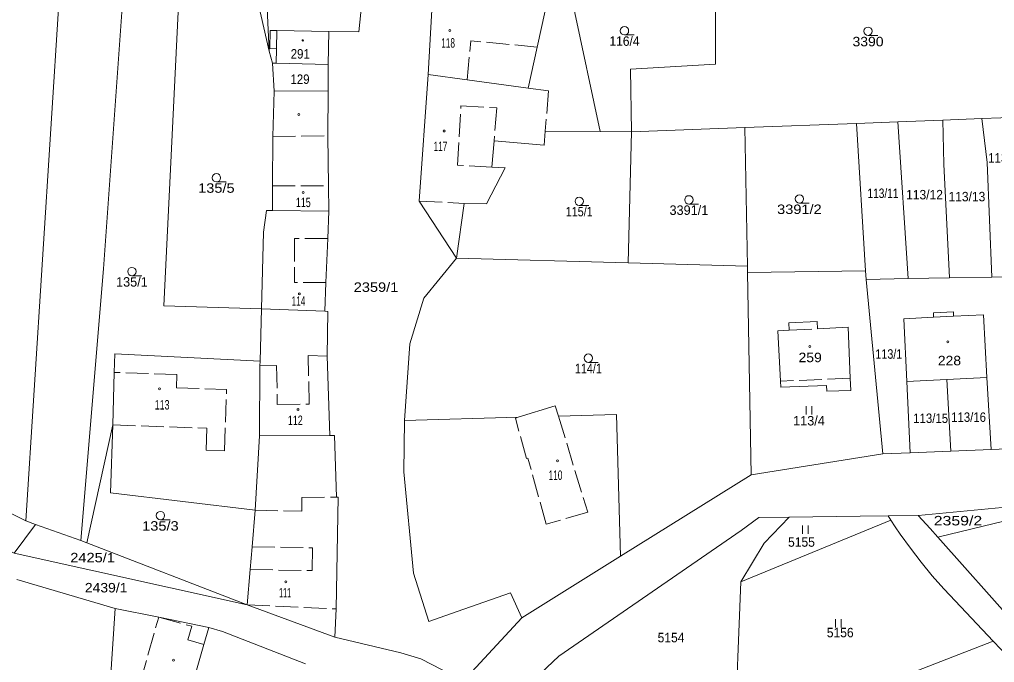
# Model space of a CAD drawing. Extents: x -590528 to -586543, y -1119609 to -1116685.
# Drawn here: x -588705.8 to -588531, y -1118396.7 to -1118281.3 of the extents above; entities that cross this region are included whole.
import ezdxf
from ezdxf.enums import TextEntityAlignment as Align

# ---------------------------------------------------------------- set-up
doc = ezdxf.new("R2010")
doc.units = 0
doc.header["$LTSCALE"] = 0.68
doc.linetypes.add('LONG_DASHED', pattern=[7.5, 6, -1.5])
for name, color, linetype, lineweight in [('1', 7, 'Continuous', 13), ('2', 7, 'LONG_DASHED', 13), ('3', 7, 'Continuous', 13), ('6', 7, 'Continuous', 13)]:
    doc.layers.add(name, color=color, linetype=linetype, lineweight=lineweight)

msp = doc.modelspace()

# ---------------------------------------------------------------- linework, layer by layer
at = {"layer": '1'}
for p, q in [((-588696.04, -1118236.25), (-588704.69, -1118371.28)), ((-588684.37, -1118236.36), (-588690.78, -1118326.07)), ((-588675.24, -1118236.53), (-588679.96, -1118332.69)), ((-588632.53, -1118291.22), (-588631.71, -1118276.27)), ((-588580.97, -1118277.25), (-588581.01, -1118289.34)), ((-588611.53, -1118279.79), (-588612.95, -1118286.29)), ((-588606.41, -1118279.31), (-588601.67, -1118301.43)), ((-588660.94, -1118286.57), (-588660.88, -1118283.31)), ((-588660.88, -1118283.31), (-588659.68, -1118283.33)), ((-588659.68, -1118283.33), (-588650.37, -1118283.5)), ((-588650.46, -1118289.41), (-588650.37, -1118283.5)), ((-588650.37, -1118283.5), (-588644.97, -1118283.56)), ((-588660.43, -1118289.2), (-588661.02, -1118287)), ((-588659.74, -1118286.58), (-588660.94, -1118286.57)), ((-588659.79, -1118289.21), (-588659.74, -1118286.58)), ((-588612.95, -1118286.29), (-588614.57, -1118293.65)), ((-588660.43, -1118289.2), (-588660.17, -1118294.19)), ((-588581.01, -1118289.34), (-588596.22, -1118290.26)), ((-588596.22, -1118290.26), (-588596.08, -1118301.47)), ((-588634.12, -1118313.92), (-588632.53, -1118291.22)), ((-588660.17, -1118294.19), (-588660.38, -1118302.35)), ((-588660.17, -1118294.19), (-588650.48, -1118294.17)), ((-588611.54, -1118301.37), (-588611.75, -1118303.88)), ((-588575.72, -1118300.72), (-588596.08, -1118301.47)), ((-588555.73, -1118299.98), (-588575.72, -1118300.72)), ((-588660.38, -1118302.35), (-588660.45, -1118311.21)), ((-588621.12, -1118307.84), (-588620.72, -1118303.12)), ((-588611.75, -1118303.88), (-588620.72, -1118303.12)), ((-588596.08, -1118301.47), (-588596.65, -1118325.01)), ((-588622.04, -1118314.41), (-588618.72, -1118307.98)), ((-588618.72, -1118307.98), (-588621.12, -1118307.84)), ((-588660.45, -1118311.21), (-588660.45, -1118315.64)), ((-588634.12, -1118313.92), (-588627.44, -1118324.18)), ((-588627.44, -1118324.18), (-588626.08, -1118314.36)), ((-588626.08, -1118314.36), (-588622.04, -1118314.41)), ((-588661.54, -1118315.62), (-588662.09, -1118319.49)), ((-588662.09, -1118319.49), (-588662.4, -1118333.22)), ((-588633.3, -1118331.32), (-588627.44, -1118324.18)), ((-588690.78, -1118326.07), (-588694.8, -1118374.81)), ((-588554.07, -1118326.42), (-588575.26, -1118326.74)), ((-588575.26, -1118326.74), (-588574.61, -1118363.03)), ((-588528.46, -1118327.49), (-588531.44, -1118327.55)), ((-588650.89, -1118328.55), (-588651.09, -1118333.69)), ((-588679.96, -1118332.69), (-588662.4, -1118333.22)), ((-588650.63, -1118341.76), (-588650.52, -1118333.71)), ((-588688.74, -1118341.3), (-588662.67, -1118342.61)), ((-588650.63, -1118341.76), (-588650.16, -1118355.99)), ((-588662.7, -1118343.49), (-588662.77, -1118356.01)), ((-588546.06, -1118359.08), (-588546.69, -1118346.28)), ((-588539.5, -1118345.91), (-588538.81, -1118358.78)), ((-588532.32, -1118345.56), (-588531.56, -1118358.48)), ((-588569.26, -1118347.32), (-588561.09, -1118346.99)), ((-588561.09, -1118346.99), (-588561.05, -1118348.04)), ((-588561.05, -1118348.04), (-588556.75, -1118347.87)), ((-588636.78, -1118353.29), (-588616.41, -1118352.7)), ((-588609.18, -1118352.49), (-588598.76, -1118352.19)), ((-588598.76, -1118352.19), (-588598.02, -1118377.63)), ((-588689.11, -1118354.08), (-588693.73, -1118375.21)), ((-588663.56, -1118369.38), (-588662.77, -1118356.01)), ((-588574.61, -1118363.03), (-588550.98, -1118359.27)), ((-588636.88, -1118362.51), (-588635.13, -1118380.66)), ((-588598.02, -1118377.63), (-588574.61, -1118363.03)), ((-588711.91, -1118367.77), (-588704.69, -1118371.28)), ((-588689.47, -1118366.26), (-588663.56, -1118369.38)), ((-588649.04, -1118387.09), (-588648.64, -1118367.04)), ((-588544.65, -1118370.34), (-588512.81, -1118367.3)), ((-588664.12, -1118375.92), (-588663.56, -1118369.38)), ((-588518.04, -1118368.57), (-588541.12, -1118374.2)), ((-588704.69, -1118371.28), (-588702.93, -1118371.91)), ((-588567.8, -1118370.6), (-588572.29, -1118375.3)), ((-588549.55, -1118371.14), (-588550.04, -1118370.4)), ((-588549.55, -1118371.14), (-588548.75, -1118372.34)), ((-588702.93, -1118371.91), (-588694.8, -1118374.81)), ((-588576.42, -1118373.01), (-588609.09, -1118395.57)), ((-588542.49, -1118372.66), (-588541.12, -1118374.2)), ((-588693.73, -1118375.21), (-588694.8, -1118374.81)), ((-588541.12, -1118374.2), (-588525.61, -1118391.67)), ((-588693.73, -1118375.21), (-588665, -1118386.32)), ((-588572.29, -1118375.3), (-588576.45, -1118382.23)), ((-588706.76, -1118377.06), (-588665, -1118386.32)), ((-588615.72, -1118388.66), (-588598.02, -1118377.63)), ((-588706.32, -1118381.81), (-588688.67, -1118386.99)), ((-588635.13, -1118380.66), (-588632.4, -1118389.34)), ((-588617.74, -1118384.22), (-588615.72, -1118388.66)), ((-588688.67, -1118386.99), (-588689.63, -1118401.93)), ((-588626.19, -1118399.97), (-588615.72, -1118388.66)), ((-588671.84, -1118390.41), (-588669.43, -1118391.16)), ((-588669.43, -1118391.16), (-588654.55, -1118396.94)), ((-588649.25, -1118392.14), (-588637.46, -1118394.95)), ((-588675.46, -1118402.73), (-588672.74, -1118393.49)), ((-588577.61, -1118410.81), (-588531.17, -1118392.89)), ((-588531.17, -1118392.89), (-588501.37, -1118424.43))]:
    msp.add_line(p, q, dxfattribs=at)
for points in [[(-588664.12, -1118273.62), (-588661.02, -1118287), (-588662.35, -1118258.78)], [(-588648.73, -1118261.95), (-588642.73, -1118262.17), (-588644.97, -1118283.56)], [(-588660.43, -1118289.2), (-588659.79, -1118289.21), (-588650.46, -1118289.41)], [(-588650.46, -1118289.41), (-588650.48, -1118294.17), (-588650.52, -1118302.23)], [(-588632.53, -1118291.22), (-588625.56, -1118292.16), (-588614.57, -1118293.65)], [(-588555.73, -1118299.98), (-588548.3, -1118299.69), (-588540.24, -1118299.39), (-588533.24, -1118299.13), (-588526.42, -1118298.88)], [(-588540.24, -1118299.39), (-588540.02, -1118307.32), (-588539.06, -1118327.69)], [(-588533.24, -1118299.13), (-588532.27, -1118307.02), (-588531.44, -1118327.55)], [(-588596.08, -1118301.47), (-588601.67, -1118301.43), (-588611.54, -1118301.37)], [(-588575.72, -1118300.72), (-588575.28, -1118325.58), (-588575.26, -1118326.74)], [(-588555.73, -1118299.98), (-588554.07, -1118326.42), (-588553.98, -1118327.96), (-588546.47, -1118327.82)], [(-588548.3, -1118299.69), (-588546.47, -1118327.82), (-588539.06, -1118327.69), (-588531.44, -1118327.55)], [(-588650.52, -1118302.23), (-588650.39, -1118311.21), (-588650.32, -1118315.71)], [(-588650.32, -1118315.71), (-588660.45, -1118315.64), (-588661.54, -1118315.62)], [(-588650.32, -1118315.71), (-588650.54, -1118320.66), (-588650.89, -1118328.55)], [(-588627.44, -1118324.18), (-588596.65, -1118325.01), (-588575.28, -1118325.58)], [(-588531.56, -1118358.48), (-588538.81, -1118358.78), (-588546.06, -1118359.08), (-588550.98, -1118359.27), (-588553.98, -1118327.96)], [(-588636.88, -1118362.51), (-588636.78, -1118353.29), (-588635.84, -1118339.53), (-588633.3, -1118331.32)], [(-588662.7, -1118343.49), (-588662.67, -1118342.61), (-588662.4, -1118333.22)], [(-588662.4, -1118333.22), (-588651.09, -1118333.69), (-588650.52, -1118333.71)], [(-588547.24, -1118335.03), (-588541.89, -1118334.76), (-588541.92, -1118333.96)], [(-588541.92, -1118333.96), (-588538.34, -1118333.78), (-588538.34, -1118334.58), (-588532.96, -1118334.31)], [(-588532.96, -1118334.31), (-588532.32, -1118345.56), (-588539.5, -1118345.91)], [(-588569.79, -1118337.2), (-588567.78, -1118337.1), (-588567.85, -1118335.77), (-588562.78, -1118335.51), (-588562.71, -1118336.83), (-588557.2, -1118336.55)], [(-588539.5, -1118345.91), (-588546.69, -1118346.28), (-588547.24, -1118335.03)], [(-588569.79, -1118337.2), (-588569.32, -1118346.24), (-588569.26, -1118347.32)], [(-588557.2, -1118336.55), (-588556.84, -1118345.67), (-588556.75, -1118347.87)], [(-588688.74, -1118341.3), (-588688.84, -1118344.66), (-588689.11, -1118354.08), (-588689.47, -1118366.26)], [(-588616.41, -1118352.7), (-588609.74, -1118350.66), (-588609.18, -1118352.49)], [(-588649.31, -1118355.99), (-588650.16, -1118355.99), (-588662.77, -1118356.01)], [(-588648.64, -1118367.04), (-588648.97, -1118367.02), (-588649.31, -1118355.99)], [(-588531.56, -1118358.48), (-588527.19, -1118358.3), (-588518.99, -1118357.97)], [(-588742.05, -1118360.45), (-588706.76, -1118377.06), (-588702.93, -1118371.91)], [(-588577.61, -1118410.81), (-588576.45, -1118382.23), (-588549.55, -1118371.14)], [(-588542.49, -1118372.66), (-588544.65, -1118370.34), (-588550.04, -1118370.4), (-588555.03, -1118370.45), (-588567.8, -1118370.6), (-588573.22, -1118370.67), (-588576.42, -1118373.01)], [(-588548.75, -1118372.34), (-588547.88, -1118373.65), (-588546.05, -1118376.21)], [(-588649.04, -1118387.09), (-588649.25, -1118392.14), (-588665, -1118386.32), (-588664.47, -1118380.02), (-588664.12, -1118375.92)], [(-588546.05, -1118376.21), (-588544.14, -1118378.7), (-588542.14, -1118381.13), (-588540.05, -1118383.49), (-588538.97, -1118384.64), (-588531.17, -1118392.89)], [(-588632.4, -1118389.34), (-588628.5, -1118387.98), (-588617.74, -1118384.22)], [(-588688.67, -1118386.99), (-588680.86, -1118388.53), (-588671.84, -1118390.41), (-588672.74, -1118393.49)], [(-588637.46, -1118394.95), (-588633.84, -1118396.05), (-588626.19, -1118399.97)], [(-588609.09, -1118395.57), (-588612.31, -1118398.61), (-588617.96, -1118403.95)]]:
    msp.add_lwpolyline(points, dxfattribs=at)
at = {"layer": '2'}
for p, q in [((-588659.74, -1118286.58), (-588659.68, -1118283.33)), ((-588625.56, -1118292.16), (-588624.9, -1118285.16)), ((-588612.95, -1118286.29), (-588624.9, -1118285.16)), ((-588614.57, -1118293.65), (-588610.92, -1118294.15)), ((-588610.92, -1118294.15), (-588611.54, -1118301.37)), ((-588627.27, -1118307.48), (-588626.64, -1118296.82)), ((-588626.64, -1118296.82), (-588620.2, -1118297.2)), ((-588620.2, -1118297.2), (-588620.72, -1118303.12)), ((-588660.38, -1118302.35), (-588650.52, -1118302.23)), ((-588621.12, -1118307.84), (-588627.27, -1118307.48)), ((-588660.45, -1118311.21), (-588650.39, -1118311.21)), ((-588634.12, -1118313.92), (-588626.08, -1118314.36)), ((-588650.89, -1118328.55), (-588656.52, -1118328.55)), ((-588541.89, -1118334.76), (-588538.34, -1118334.58)), ((-588567.78, -1118337.1), (-588562.71, -1118336.83)), ((-588653.89, -1118350.34), (-588654.02, -1118341.64)), ((-588654.02, -1118341.64), (-588650.63, -1118341.76)), ((-588677.6, -1118345.05), (-588688.84, -1118344.66)), ((-588677.68, -1118347.42), (-588677.6, -1118345.05)), ((-588662.7, -1118343.49), (-588659.7, -1118343.43)), ((-588659.7, -1118343.43), (-588659.59, -1118350.43)), ((-588556.84, -1118345.67), (-588569.32, -1118346.24)), ((-588677.68, -1118347.42), (-588668.68, -1118347.74)), ((-588669.06, -1118358.7), (-588668.68, -1118347.74)), ((-588659.59, -1118350.43), (-588653.89, -1118350.34)), ((-588609.18, -1118352.49), (-588603.91, -1118369.71)), ((-588689.11, -1118354.08), (-588672.23, -1118354.68)), ((-588672.23, -1118354.68), (-588672.37, -1118358.58)), ((-588672.37, -1118358.58), (-588669.06, -1118358.7)), ((-588664.12, -1118375.92), (-588653.27, -1118376.11)), ((-588653.27, -1118376.11), (-588653.34, -1118380.21)), ((-588664.47, -1118380.02), (-588653.34, -1118380.21)), ((-588665, -1118386.32), (-588649.04, -1118387.09)), ((-588684.17, -1118400.27), (-588680.86, -1118388.53)), ((-588680.86, -1118388.53), (-588674.94, -1118390.2)), ((-588675.62, -1118392.61), (-588674.94, -1118390.2)), ((-588675.62, -1118392.61), (-588672.74, -1118393.49))]:
    msp.add_line(p, q, dxfattribs=at)
for points in [[(-588650.54, -1118320.66), (-588656.52, -1118320.66), (-588656.52, -1118328.55)], [(-588603.91, -1118369.71), (-588611.36, -1118371.89), (-588614.63, -1118360.02), (-588614.92, -1118360.11), (-588616.87, -1118352.84), (-588616.41, -1118352.7)], [(-588663.56, -1118369.38), (-588655.17, -1118369.54), (-588655.17, -1118367.11), (-588648.97, -1118367.02)]]:
    msp.add_lwpolyline(points, dxfattribs=at)
at = {"layer": '6'}
for p, q in [((-588597.32, -1118284.12), (-588595.57, -1118284.12)), ((-588553.64, -1118284.21), (-588551.89, -1118284.21)), ((-588670.51, -1118310.48), (-588668.76, -1118310.48)), ((-588605.44, -1118314.71), (-588603.69, -1118314.71)), ((-588585.77, -1118314.45), (-588584.02, -1118314.45)), ((-588565.95, -1118314.29), (-588564.2, -1118314.29)), ((-588685.66, -1118327.32), (-588683.91, -1118327.32)), ((-588603.8, -1118342.85), (-588602.05, -1118342.85)), ((-588564.73, -1118352.22), (-588564.73, -1118350.72)), ((-588563.73, -1118352.22), (-588563.73, -1118350.72)), ((-588680.55, -1118371.09), (-588678.8, -1118371.09)), ((-588565.38, -1118373.62), (-588565.38, -1118372.12)), ((-588564.38, -1118373.62), (-588564.38, -1118372.12)), ((-588559.45, -1118390.42), (-588559.45, -1118388.92)), ((-588558.45, -1118390.42), (-588558.45, -1118388.92))]:
    msp.add_line(p, q, dxfattribs=at)
for centre, radius in [((-588628.6402, -1118283.3304), 0.175), ((-588597.32, -1118283.37), 0.75), ((-588553.64, -1118283.46), 0.75), ((-588655.0301, -1118285.1002), 0.1172), ((-588655.7202, -1118298.4104), 0.175), ((-588629.6402, -1118301.3504), 0.175), ((-588670.51, -1118309.73), 0.75), ((-588654.9602, -1118312.4004), 0.175), ((-588605.44, -1118313.96), 0.75), ((-588585.77, -1118313.7), 0.75), ((-588565.95, -1118313.54), 0.75), ((-588685.66, -1118326.57), 0.75), ((-588655.6302, -1118330.5504), 0.175), ((-588564.0902, -1118339.9904), 0.175), ((-588539.3402, -1118339.1904), 0.175), ((-588603.8, -1118342.1), 0.75), ((-588680.7002, -1118347.5804), 0.175), ((-588655.8702, -1118351.3204), 0.175), ((-588609.3102, -1118360.5104), 0.175), ((-588680.55, -1118370.34), 0.75), ((-588658.0602, -1118382.2304), 0.175), ((-588678.2202, -1118396.2704), 0.175)]:
    msp.add_circle(centre, radius, dxfattribs=at)

# ---------------------------------------------------------------- texts
at = {"layer": '3'}
for s, width, p in [('118', 0.65, (-588628.95, -1118286.4)), ('116/4', 0.95, (-588597.32, -1118286.07)), ('3390', 1.1, (-588553.64, -1118286.16)), ('291', 0.9, (-588655.4705, -1118288.36)), ('129', 0.9, (-588655.5105, -1118292.9)), ('117', 0.65, (-588630.3305, -1118304.96)), ('113/14', 0.9, (-588528.96, -1118307.01)), ('135/5', 1.15, (-588670.5105, -1118312.43)), ('113/11', 0.8, (-588550.96, -1118313.37)), ('113/12', 0.95, (-588543.51, -1118313.62)), ('115', 0.7, (-588654.9205, -1118315)), ('113/13', 0.95, (-588535.91, -1118313.97)), ('115/1', 0.85, (-588605.4405, -1118316.66)), ('3391/2', 1.15, (-588565.95, -1118316.24)), ('2359/1', 1.15, (-588641.8805, -1118330.21)), ('114', 0.65, (-588655.79, -1118332.71)), ('259', 1.1, (-588564.0205, -1118342.82)), ('113/1', 0.85, (-588549.91, -1118342.2)), ('114/1', 0.85, (-588603.8, -1118344.8)), ('228', 1.1, (-588539.0405, -1118343.38)), ('113', 0.7, (-588680.24, -1118351.31)), ('113/15', 0.9, (-588542.41, -1118353.73)), ('113/16', 0.9, (-588535.61, -1118353.53)), ('112', 0.7, (-588656.3505, -1118354.09)), ('110', 0.65, (-588609.6905, -1118363.94)), ('135/3', 1.15, (-588680.55, -1118373.04)), ('2359/2', 1.25, (-588537.5105, -1118372.1)), ('2425/1', 1.15, (-588692.7105, -1118378.72)), ('2439/1', 1.1, (-588690.28, -1118384.12)), ('111', 0.5, (-588658.19, -1118385.03))]:
    msp.add_text(s, height=1.7, dxfattribs=dict(at, width=width)).set_placement(p, align=Align.CENTER)
for s, p in [('3391/1', (-588585.77, -1118316.4)), ('135/1', (-588685.661, -1118329.27)), ('113/4', (-588564.23, -1118354.17))]:
    msp.add_text(s, height=1.7, dxfattribs=at).set_placement(p, align=Align.CENTER)
at = {"layer": '3', "width": 0.95}
for s, p in [('5155', (-588567.983, -1118375.93)), ('5156', (-588561.033, -1118392.17)), ('5154', (-588591.373, -1118393.07))]:
    msp.add_text(s, height=1.7, dxfattribs=at).set_placement(p)

doc.saveas('drawing.dxf')
